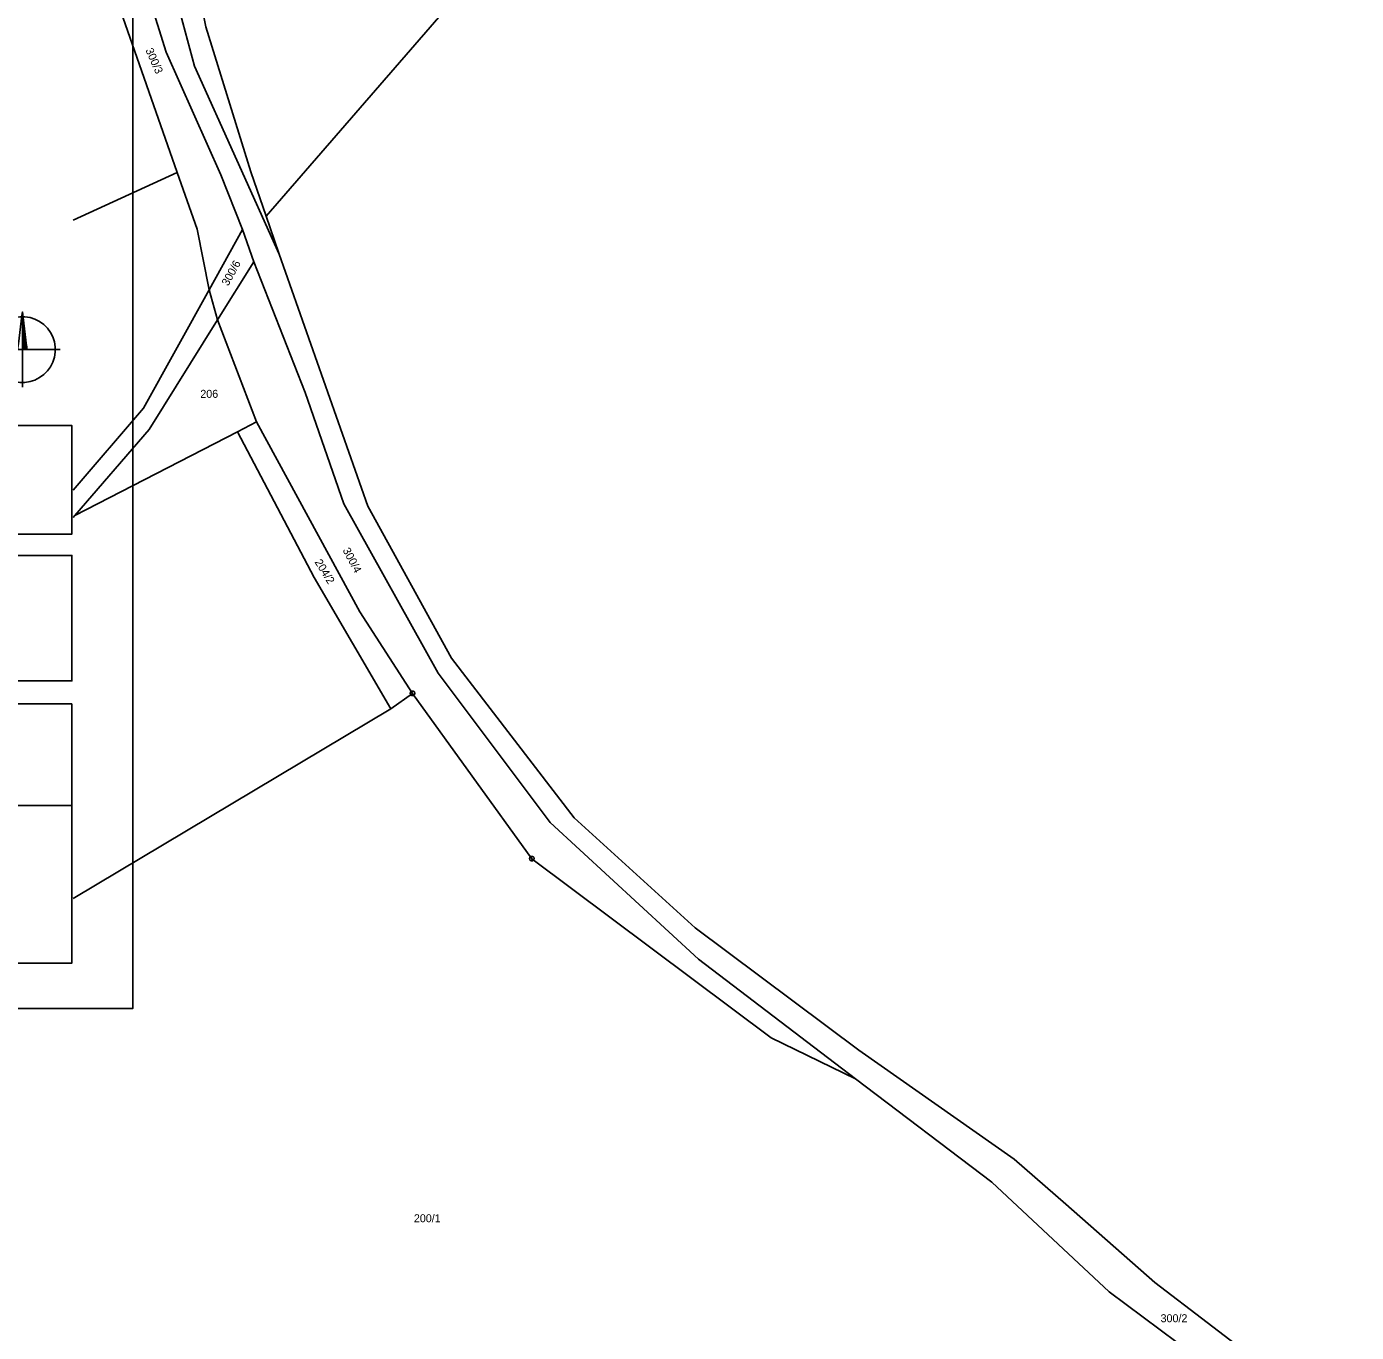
# Model space of a CAD drawing. Extents: x -779723 to -777378, y -1011169 to -1009297.
# Drawn here: x -778959.2 to -778676.8, y -1010756.7 to -1010479.3 of the extents above; entities that cross this region are included whole.
import ezdxf

# ---------------------------------------------------------------- set-up
doc = ezdxf.new("R2010")
doc.units = 0
for name, color, linetype in [('Default', 7, 'Continuous'), ('KN_HRANICE', 7, 'Continuous'), ('KN_PARCELY', 7, 'Continuous'), ('LEGENDA', 7, 'Continuous'), ('tabulka', 7, 'Continuous')]:
    doc.layers.add(name, color=color, linetype=linetype)

# ---------------------------------------------------------------- blocks, each defined once
blk = doc.blocks.new('105')
at = {"layer": 'Default'}
blk.add_line((-0.12, 0), (0.12, 0), dxfattribs=at)
blk.add_lwpolyline([(0.15, 0.48), (0.4, 0.3), (0.5, 0.01), (0.4, -0.28), (0.15, -0.46), (-0.16, -0.46), (-0.41, -0.28), (-0.51, 0.01), (-0.41, 0.3), (-0.16, 0.48), (0.15, 0.48)], dxfattribs=at)
blk = doc.blocks.new('SEVER')
at = {"layer": 'Default'}
for points in [[(5.5, 69.8), (16.3, 68.1), (26.7, 64.7), (36.5, 59.7), (45.4, 53.2), (53.2, 45.4), (59.7, 36.5), (64.7, 26.7), (68.1, 16.3), (69.8, 5.5), (69.8, -5.5), (68.1, -16.3), (64.7, -26.7), (59.7, -36.5), (53.2, -45.4), (45.4, -53.2), (36.5, -59.7), (26.7, -64.7), (16.3, -68.1), (5.5, -69.8), (-5.5, -69.8), (-16.3, -68.1), (-26.7, -64.7), (-36.5, -59.7), (-45.4, -53.2), (-53.2, -45.4), (-59.7, -36.5), (-64.7, -26.7), (-68.1, -16.3), (-69.8, -5.5), (-69.8, 5.5), (-68.1, 16.3), (-64.7, 26.7), (-59.7, 36.5), (-53.2, 45.4), (-45.4, 53.2), (-36.5, 59.7), (-26.7, 64.7), (-16.3, 68.1), (-5.5, 69.8), (5.5, 69.8)], [(-10, 0), (-8.5, 12), (-7, 24), (-5.5, 36), (-4, 48), (-2.5, 60), (-1, 72), (0, 80), (1.5, 68), (3, 56), (4.5, 44), (6, 32), (7.5, 20), (9, 8), (10, 0), (9.2, 0.8), (9.2, 5.6), (8.4, 12), (8.4, 0.8), (7.6, 0.8), (7.6, 13.5), (7.6, 18.4), (6.8, 24.8), (6.8, 12.1), (6.8, 0.8), (6, 0.8), (6, 13.5), (6, 26.2), (6, 31.2), (5.2, 36.8), (5.2, 24.1), (5.2, 11.4), (5.2, 0.8), (4.4, 0.8), (4.4, 13.5), (4.4, 26.2), (4.4, 38.9), (4.4, 43.2), (3.6, 50.4), (3.6, 37.7), (3.6, 25), (3.6, 12.3), (3.6, 0.8), (2.8, 0.8), (2.8, 13.5), (2.8, 26.2), (2.8, 38.9), (2.8, 51.6), (2.8, 56), (2, 63.2), (2, 50.5), (2, 37.8), (2, 25.1), (2, 12.4), (2, 0.8), (1.2, 0.8), (1.2, 13.5), (1.2, 26.2), (1.2, 38.9), (1.2, 51.6), (1.2, 64.3), (1.2, 69.6), (0.4, 76), (0.4, 63.3), (0.4, 50.6), (0.4, 37.9), (0.4, 25.2), (0.4, 12.5), (0.4, 0.8)], [(0, 80), (0, 67.3), (0, 54.6), (0, 41.9), (0, 29.2), (0, 16.5), (0, 3.8), (0, -8.9), (0, -21.6), (0, -34.3), (0, -47), (0, -59.7), (0, -72.4), (0, -80)], [(80, 0), (67.3, 0), (54.6, 0), (41.9, 0), (29.2, 0), (16.5, 0), (3.8, 0), (-8.9, 0), (-21.6, 0), (-34.3, 0), (-47, 0), (-59.7, 0), (-72.4, 0), (-80, 0)]]:
    blk.add_lwpolyline(points, dxfattribs=at)

msp = doc.modelspace()

# ---------------------------------------------------------------- linework, layer by layer
at = {"layer": 'KN_HRANICE'}
for p, q in [((-778929.7, -1010437.49), (-778921.17, -1010479.33)), ((-778935.36, -1010444.3), (-778923.56, -1010487.7)), ((-778929.57, -1010484.72), (-778940.29, -1010450.68)), ((-778945.86, -1010456.94), (-778927.24, -1010510.3)), ((-778869.31, -1010474.62), (-778908.34, -1010519.61)), ((-778921.17, -1010479.33), (-778911.59, -1010510.13)), ((-778918, -1010510.77), (-778929.57, -1010484.72)), ((-778923.56, -1010487.7), (-778905.58, -1010527.64)), ((-778949.34, -1010520.45), (-778927.24, -1010510.3)), ((-778927.24, -1010510.3), (-778923.04, -1010522.33)), ((-778913.36, -1010522.39), (-778918, -1010510.77)), ((-778911.59, -1010510.13), (-778908.34, -1010519.61)), ((-778908.34, -1010519.61), (-778907.5, -1010522.06)), ((-778923.04, -1010522.33), (-778920.49, -1010535.22)), ((-778913.36, -1010522.39), (-778920.49, -1010535.22)), ((-778910.96, -1010529.3), (-778913.36, -1010522.39)), ((-778907.5, -1010522.06), (-778905.58, -1010527.64)), ((-778905.58, -1010527.64), (-778886.77, -1010581.17)), ((-778918.72, -1010541.61), (-778910.96, -1010529.3)), ((-778900.07, -1010557.06), (-778910.96, -1010529.3)), ((-778920.49, -1010535.22), (-778934.39, -1010560.4)), ((-778920.49, -1010535.22), (-778918.72, -1010541.61)), ((-778933.19, -1010564.92), (-778918.72, -1010541.61)), ((-778918.72, -1010541.61), (-778910.38, -1010563.3)), ((-778891.89, -1010580.73), (-778900.07, -1010557.06)), ((-778934.39, -1010560.4), (-778949.34, -1010577.76)), ((-778949, -1010583.2), (-778933.19, -1010564.92)), ((-778949, -1010583.2), (-778914.41, -1010565.37)), ((-778914.41, -1010565.37), (-778910.38, -1010563.3)), ((-778914.41, -1010565.37), (-778898.15, -1010596.34)), ((-778888.45, -1010603.65), (-778910.38, -1010563.3)), ((-778871.79, -1010616.66), (-778891.89, -1010580.73)), ((-778886.77, -1010581.17), (-778868.96, -1010613.49)), ((-778949.34, -1010583.59), (-778949, -1010583.2)), ((-778898.15, -1010596.34), (-778881.89, -1010624.28)), ((-778888.45, -1010603.65), (-778877.27, -1010620.97)), ((-778868.96, -1010613.49), (-778842.93, -1010647.4)), ((-778848.04, -1010648.37), (-778871.79, -1010616.66)), ((-778877.27, -1010620.97), (-778881.89, -1010624.28)), ((-778877.27, -1010620.97), (-778851.92, -1010656.09)), ((-778881.89, -1010624.28), (-778949.34, -1010664.57)), ((-778842.93, -1010647.4), (-778817.25, -1010670.8)), ((-778816.52, -1010677.44), (-778848.04, -1010648.37)), ((-778851.92, -1010656.09), (-778801.09, -1010694.14)), ((-778817.25, -1010670.8), (-778782.47, -1010696.78)), ((-778783.19, -1010702.88), (-778816.52, -1010677.44)), ((-778801.09, -1010694.14), (-778783.19, -1010702.88)), ((-778782.47, -1010696.78), (-778749.49, -1010719.92)), ((-778783.19, -1010702.88), (-778754.23, -1010724.83)), ((-778749.49, -1010719.92), (-778738.54, -1010729.52)), ((-778754.23, -1010724.83), (-778729.33, -1010748.14)), ((-778738.54, -1010729.52), (-778719.6, -1010746.13)), ((-778719.6, -1010746.13), (-778676.79, -1010778.85)), ((-778729.33, -1010748.14), (-778714.89, -1010758.88))]:
    msp.add_line(p, q, dxfattribs=at)
at = {"layer": 'LEGENDA'}
msp.add_lwpolyline([(-779530.66, -1010687.91), (-778936.66, -1010687.91), (-778936.66, -1010267.91), (-779530.66, -1010267.91)], close=True, dxfattribs=at)
at = {"layer": 'tabulka'}
for p, q in [((-779108.28, -1010623.16), (-778949.63, -1010623.16)), ((-779108.28, -1010644.77), (-778949.63, -1010644.77))]:
    msp.add_line(p, q, dxfattribs=at)
for points in [[(-779108.28, -1010564.07), (-778949.63, -1010564.07), (-778949.63, -1010587.13), (-779108.28, -1010587.13)], [(-779108.28, -1010591.65), (-778949.63, -1010591.65), (-778949.63, -1010618.34), (-779108.28, -1010618.34)]]:
    msp.add_lwpolyline(points, close=True, dxfattribs=at)
msp.add_lwpolyline([(-778949.63, -1010623.16), (-778949.63, -1010678.29), (-779108.28, -1010678.29), (-779108.28, -1010623.16)], dxfattribs=at)

# ---------------------------------------------------------------- block references
at = {"layer": 'KN_PARCELY'}
for p in [(-778877.27, -1010620.97), (-778851.92, -1010656.09)]:
    msp.add_blockref('105', p, dxfattribs=at)
at = {"layer": 'LEGENDA', "xscale": 0.1, "yscale": 0.10000000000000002}
msp.add_blockref('SEVER', (-778960.14, -1010547.92), dxfattribs=at)

# ---------------------------------------------------------------- texts
at = {"layer": 'KN_PARCELY'}
for s, rotation, p in [('300/3', 293.641, (-778934.03, -1010484.3)), ('300/6', 61.077, (-778916.44, -1010534.54)), ('300/4', 297.995, (-778892.17, -1010590.55)), ('204/2', 301.605, (-778898.12, -1010593.08))]:
    msp.add_text(s, height=1.7, rotation=rotation, dxfattribs=at).set_placement(p)
for s, p in [('206', (-778922.34, -1010558.18)), ('200/1', (-778876.98, -1010733.34)), ('300/2', (-778718.38, -1010754.58))]:
    msp.add_text(s, height=1.7, dxfattribs=at).set_placement(p)

doc.saveas('drawing.dxf')
